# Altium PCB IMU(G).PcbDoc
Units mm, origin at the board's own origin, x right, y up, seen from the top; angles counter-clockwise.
Board outline 35 x 59.99 mm, 2 copper layers (Top Layer, Bottom Layer); 58 components, 99 nets, 240 pads, 60 vias.
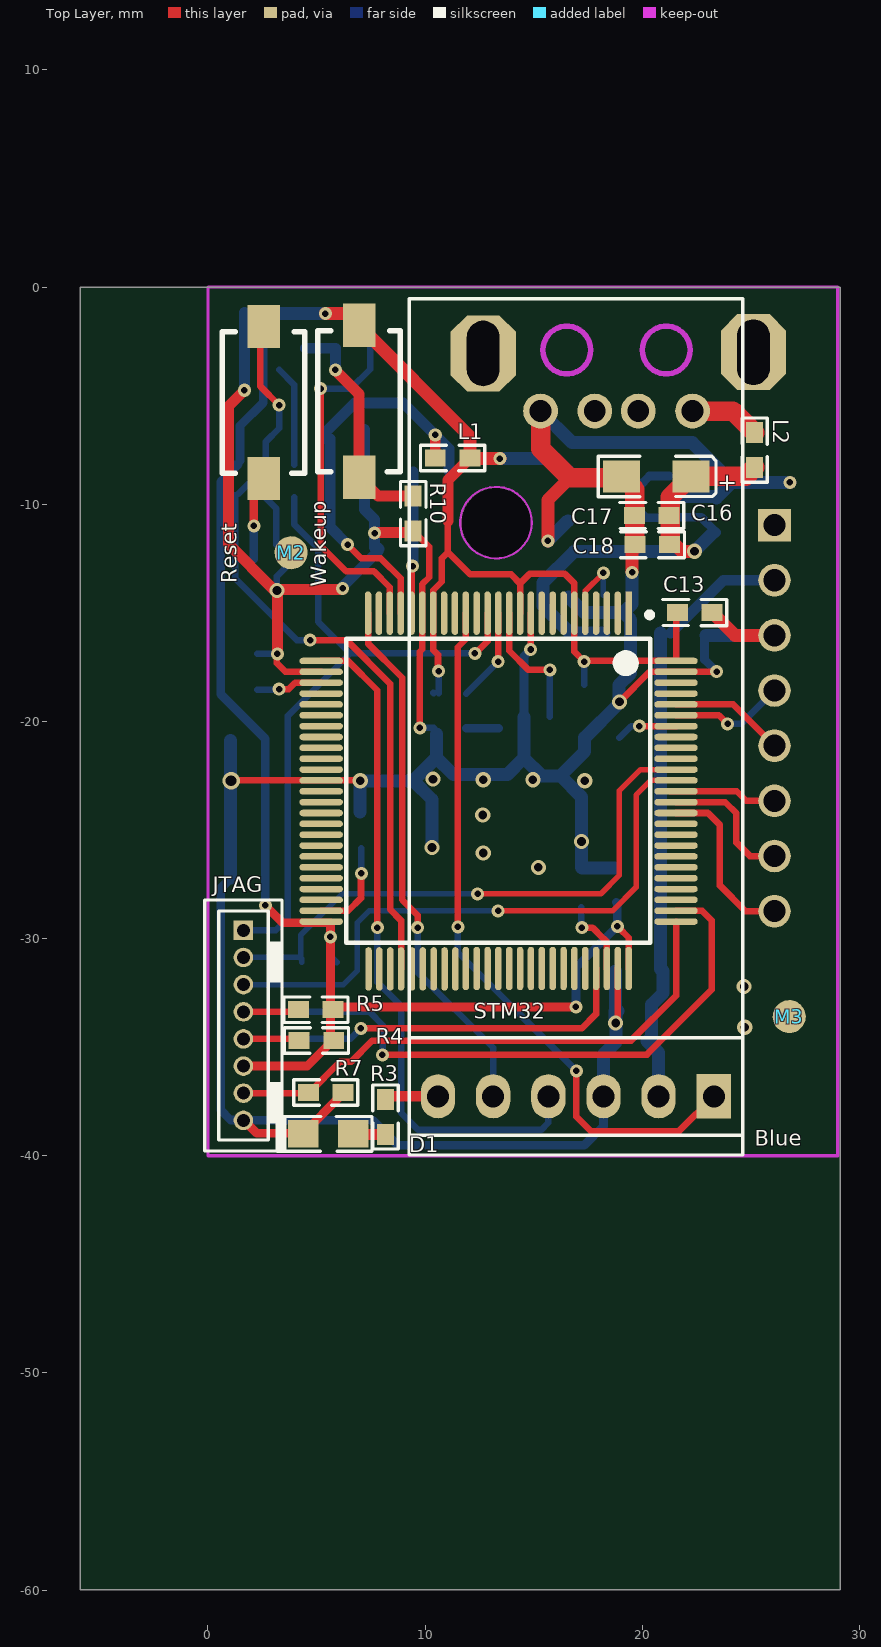
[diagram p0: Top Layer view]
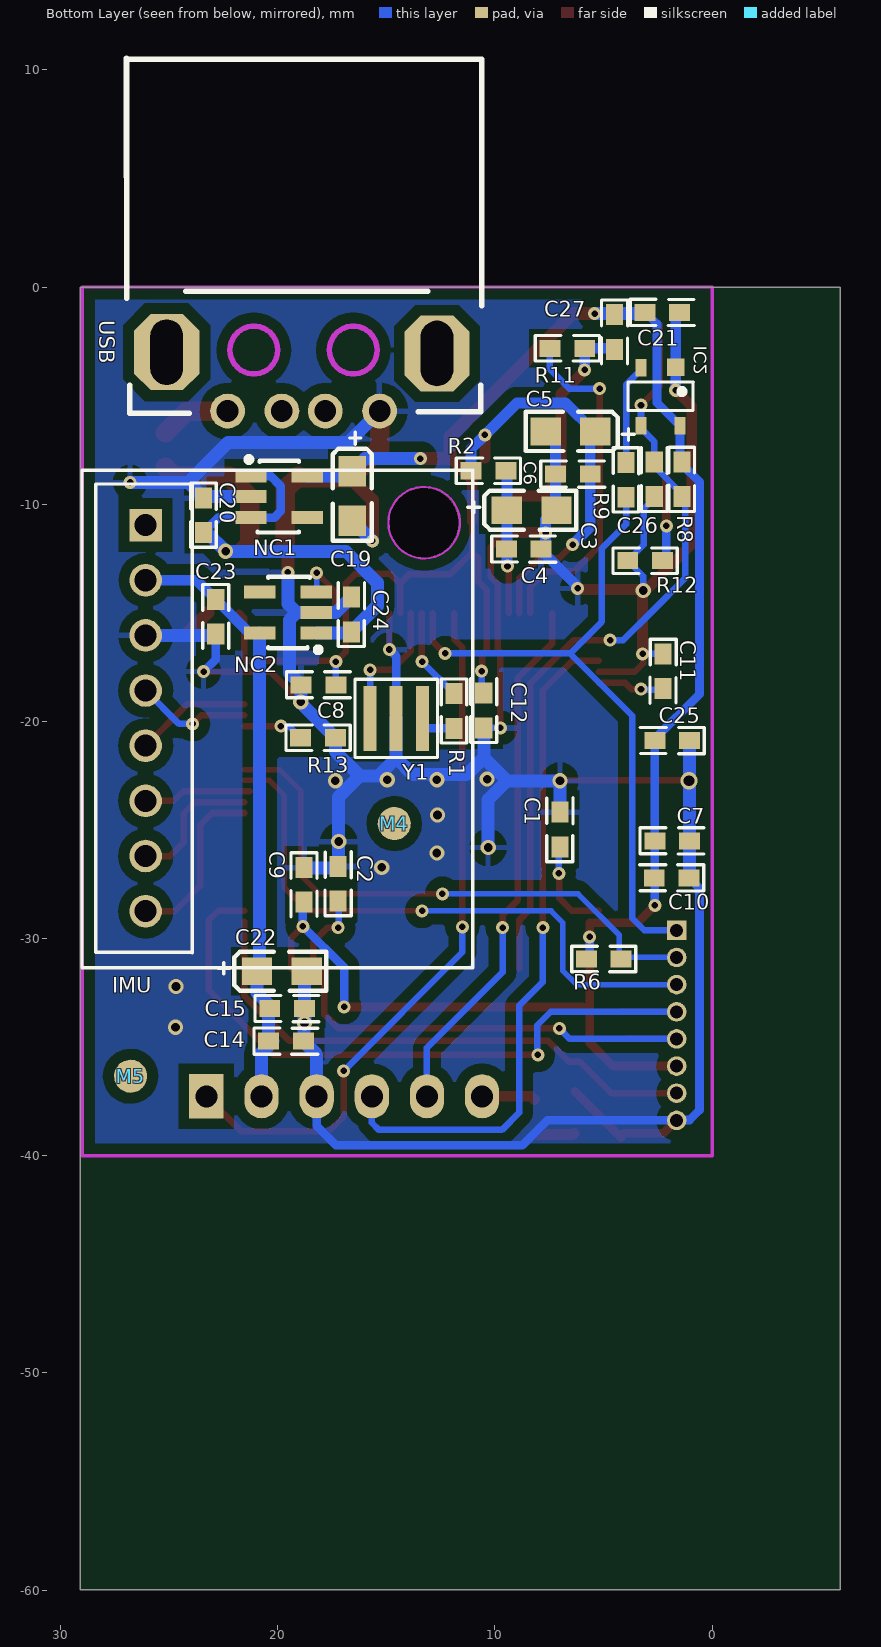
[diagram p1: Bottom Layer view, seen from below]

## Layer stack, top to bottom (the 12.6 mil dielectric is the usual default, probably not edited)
Top Layer: signal copper 0.0356
Dielectric: core 0.32, FR-4, Dk 4.8
Bottom Layer: signal copper 0.0356

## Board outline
-5.893,0 29.108,0 29.108,-59.995 -5.893,-59.995

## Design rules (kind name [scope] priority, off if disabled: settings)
Clearance [All] p1: gap=0.5
PolygonConnect [All] p1: connectstyle=Relief reliefconductorwidth=0.254 reliefentries=4 polygonreliefangle="90 Angle"
RoutingVias [All] p1: holewidth=0.711 width=1.27 viastyle="Through Hole" minholewidth=0.711 minwidth=1.27 maxholewidth=0.711 maxwidth=1.27
SilkscreenOverComponentPads [All] p1: minsilkscreentomaskgap=0.254
SolderMaskExpansion [All] p1: expansion=0.102
Width [All] p1: maxlimit=2.54 minlimit=0.2 preferedwidth=0.254
27 further rules are at their usual default settings.

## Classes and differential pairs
component class IMU_REIO: C25 C26 C27 IC2 M2 M3 M4 M5 M6 R8 R9 R10 R11 R12 R13 R18 Reset S1 S2 Wakeup
component class IMU_POW: C16 C17 C18 C19 C20 C21 C22 C23 C24 C28 C33 L2 NC1 NC2 USB
component class IMU_Blue: Blue Bluetooth C14 C15 D1 IMU JTAG P1 P2 P3 R3 R4 R5 R6 R7
component class CPU_STM32F4: C1 C2 C3 C4 C5 C6 C7 C8 C9 C10 C11 C12 C13 L1 R1 R2 STM32 Y1

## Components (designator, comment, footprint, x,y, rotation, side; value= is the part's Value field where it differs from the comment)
Blue "蓝牙模块" HC-06(35.7*15.2MM) 23.292,-37.262 r180 top locked (schematic designator P2)
C1 "1uF" 0603 7.01,-24.181 r270 bottom
C2 "1uF" 0603 17.221,-26.67 r270 bottom
C3 "1uF/16V" C-0805 8.357,-10.262 r180 bottom
C4 "100n" 0603 7.874,-12.065 r0 bottom
C5 "1uF/16V" C-0805 6.477,-6.655 r0 bottom
C6 "100n" 0603 5.613,-8.611 r0 bottom
C7 "100n" 0603 1.041,-25.502 r0 bottom
C8 "100n" 0603 17.323,-18.313 r0 bottom
C9 "100n" 0603 18.796,-28.321 r90 bottom
C10 "100n" 0603 2.667,-27.203 r180 bottom
C11 "100n" 0603 2.261,-18.491 r90 bottom
C12 "100n" 0603 10.516,-18.694 r270 bottom
C13 "100n" 0603 21.615,-14.986 r0 top
C14 "100n" 0603 18.821,-34.722 r0 bottom
C15 "100n" 0603 18.771,-33.223 r0 bottom
C16 "47uF/10V" C-A(3216-18) 22.25,-8.712 r180 top
C17 "100n" 0603 19.634,-10.516 r0 top
C18 "100n" 0603 19.66,-11.862 r0 top
C19 "4u7/10V" C-0805 16.561,-9.576 r270 bottom
C20 "100n" 0603 23.419,-9.703 r270 bottom
C21 "100n" 0603 1.499,-1.168 r0 bottom
C22 "4u7/10V" C-0805 19.863,-31.496 r180 bottom
C23 "100n" 0603 22.86,-15.977 r90 bottom
C24 "100n" 0603 16.612,-14.275 r270 bottom
C25 "100n" 0603 2.642,-20.879 r180 bottom
C26 "100n" 0603 2.667,-8.052 r270 bottom
C27 "100n" 0603 4.496,-2.87 r90 bottom
D1 "LED red" D0805 6.68,-38.989 r180 top
IC2 "MAX6315US26D2-T" TO-253 2.896,-4.47 r270 top
IMU "IMU" GY-85 18.39,-18.542 r180 bottom locked (schematic designator P1)
JTAG "CON-SIP8-2.0" PLUG1.27-8P 1.651,-33.376 r270 top (schematic designator P3)
L1 "22uH" 0603 12.065,-7.874 r180 top
L2 "22uH" 0603 25.171,-6.706 r270 top
M2 "CON-PAD" BAD_MARK 3.835,-12.217 r0 top
M3 "CON-PAD" BAD_MARK 26.772,-33.579 r0 top
M4 "CON-PAD" BAD_MARK 14.63,-24.689 r180 bottom
M5 "CON-PAD" BAD_MARK 26.772,-36.322 r180 bottom
NC1 "NCP603SN330T1G" TSSOP-5 20.371,-9.296 r180 bottom
NC2 "NCP603SN330T1G" TSSOP-5 19.101,-15.342 r0 bottom
R1 "390" 0603 11.887,-20.32 r90 bottom
R2 "47" 0603 11.1,-8.458 r180 bottom
R3 "390" 0603 8.179,-39.014 r90 top
R4 "3.9K" 0603 4.191,-34.696 r0 top
R5 "3.9K" 0603 4.166,-33.274 r0 top
R6 "3.9K" 0603 4.191,-30.937 r0 bottom
R7 "3.9K" 0603 6.223,-37.084 r180 top
R8 "47K" 0603 1.397,-9.652 r90 bottom
R9 "3.9K" 0603 3.962,-8.077 r270 bottom
R10 "47K" 0603 9.449,-11.227 r90 top
R11 "1K" 0603 5.867,-2.819 r0 bottom
R12 "10K" 0603 3.886,-12.598 r180 bottom
R13 "10K" 0603 18.948,-20.752 r180 bottom
Reset "Manual Pushbutton" KEY-6*4 2.565,-8.814 r180 top (schematic designator S1)
STM32 "STM32F40x-VG (LQFP100)" "LQFP100 (14*14)" 14.656,-21.768 r270 top locked (schematic designator IC1)
USB "车载转换头" USB-SMT 12.243,-2.997 r0 bottom (schematic designator J(USB)1)
Wakeup "Manual Pushbutton" KEY-6*4 6.96,-8.763 r180 top (schematic designator S2)
Y1 "8Mhz" XT-3.2*1.5 15.748,-19.863 r180 bottom

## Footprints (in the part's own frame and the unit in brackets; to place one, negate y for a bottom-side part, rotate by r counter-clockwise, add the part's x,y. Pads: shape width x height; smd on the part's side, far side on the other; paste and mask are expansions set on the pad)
0603 [mil]
  rect 38x31 smd: 1(0,0) 2(63,0)
  silkscreen extent -26,-24 90,24
BAD_MARK [mil] "MARK 点"
  round 60 smd mask+29.53: 0(-0.25,-0.63)
C-0805 [mm]
  rect 1.4x1.27 smd: 1(-1.096,-0.007) 2(1.19,-0.007)
  silkscreen extent -2.89,-0.91 2.1,0.92
C-A(3216-18) [mm]
  rect 1.7x1.47 smd: 1(0,0) 2(3.2,0)
  silkscreen extent -1.14,-0.92 4.28,0.94
D0805 [mm]
  rect 1.4x1.27 smd: A(0,0) K(2.286,0)
  silkscreen extent -0.87,-0.8 3.5,0.8
GY-85 [mm]
  round 3.2 hole 3.2: 0(5.12,7.698)
  rect 1.5x1.5 hole 1.016: 1(-7.697,7.584)
  round 1.5 hole 1.016: 2(-7.697,5.044) 3(-7.697,2.504) 4(-7.697,-0.036) 5(-7.697,-2.576) 6(-7.697,-5.116) 7(-7.697,-7.656) 8(-7.697,-10.196)
  silkscreen extent -10.63,-12.8 7.37,10.11
HC-06(35.7*15.2MM) [mil] "蓝牙模块"
  rect 62x80 hole 40: 1(0,0)
  oval 62x80 hole 40: 2(100,0) 3(200,0) 4(300,0) 5(400,0) 6(500,0)
  silkscreen extent -52,-1446 552,106
KEY-6*4 [mm] "2PIN"
  rect 1.5x2 smd: 1(0,0) 2(0,-7)
  silkscreen extent -1.9,-6.75 1.9,-0.25
"LQFP100 (14*14)" [mm]
  rect 2x0.3 smd: 1(-6.751,4.716)
  oval 2x0.3 smd: 2(-6.751,4.216) 3(-6.751,3.716) 4(-6.751,3.216) 5(-6.751,2.716) 6(-6.751,2.216) 7(-6.751,1.716) 8(-6.751,1.216) 9(-6.751,0.716) 10(-6.751,0.216) 11(-6.751,-0.284) 12(-6.751,-0.784) 13(-6.751,-1.284) 14(-6.751,-1.784) 15(-6.751,-2.284) 16(-6.751,-2.784) 17(-6.751,-3.284) 18(-6.751,-3.784) 19(-6.751,-4.284) 20(-6.751,-4.784) 21(-6.751,-5.284) 22(-6.751,-5.784) 23(-6.751,-6.284) 24(-6.751,-6.784) 25(-6.751,-7.284) 51(9.629,-7.264) 52(9.629,-6.764) 53(9.629,-6.264) 54(9.629,-5.764) 55(9.629,-5.264) 56(9.629,-4.764) 57(9.629,-4.264) 58(9.629,-3.764) 59(9.629,-3.264) 60(9.609,-2.784) 61(9.609,-2.284) 62(9.609,-1.784) 63(9.609,-1.284) 64(9.609,-0.784) 65(9.609,-0.284) 66(9.609,0.216) 67(9.609,0.716) 68(9.609,1.216) 69(9.609,1.716) 70(9.609,2.216) 71(9.609,2.716) 72(9.609,3.216) 73(9.609,3.716) 74(9.609,4.216) 75(9.609,4.716)
  oval 0.3x2 smd: 26(-4.551,-9.444) 27(-4.051,-9.444) 28(-3.551,-9.444) 29(-3.051,-9.444) 30(-2.551,-9.444) 31(-2.051,-9.444) 32(-1.551,-9.444) 33(-1.051,-9.444) 34(-0.551,-9.444) 35(-0.051,-9.444) 36(0.449,-9.444) 37(0.949,-9.444) 38(1.449,-9.444) 39(1.949,-9.444) 40(2.449,-9.444) 41(2.949,-9.444) 42(3.449,-9.444) 43(3.949,-9.444) 44(4.449,-9.444) 45(4.949,-9.444) 46(5.449,-9.444) 47(5.949,-9.444) 48(6.449,-9.444) 49(6.949,-9.444) 50(7.449,-9.444) 76(7.449,6.896) 77(6.949,6.896) 78(6.449,6.896) 79(5.949,6.896) 80(5.449,6.896) 81(4.949,6.896) 82(4.449,6.896) 83(3.949,6.896) 84(3.449,6.896) 85(2.949,6.896) 86(2.449,6.896) 87(1.949,6.896) 88(1.449,6.896) 89(0.949,6.896) 90(0.449,6.896) 91(-0.051,6.896) 92(-0.551,6.896) 93(-1.051,6.896) 94(-1.551,6.896) 95(-2.051,6.896) 96(-2.551,6.896) 97(-3.051,6.896) 98(-3.551,6.896) 99(-4.051,6.896) 100(-4.551,6.896)
  silkscreen extent -6.8,-8.28 8.43,5.8
PLUG1.27-8P [mm]
  rect 0.9x0.9 hole 0.6: 1(-3.756,-0.019)
  round 0.9 hole 0.6: 2(-2.506,-0.019) 3(-1.256,-0.019) 4(-0.006,-0.019) 5(1.244,-0.019) 6(2.494,-0.019) 7(3.744,-0.019) 8(4.994,-0.019)
  silkscreen extent -5.15,-1.8 6.4,1.76
TO-253 [mm]
  rect 0.8x0.8 smd far side: 1(-0.781,-1.219)
  rect 0.8x0.5 smd far side: 2(-0.761,0.381) 3(1.919,0.381) 4(1.919,-1.419)
TSSOP-5 [mm]
  rect 1.45x0.6 smd: 1(-0.864,0.595) 2(-0.864,-0.355) 3(-0.864,-1.305) 4(1.736,-1.305) 5(1.736,0.595)
  silkscreen extent -1.09,-2 1.34,1.48
USB-SMT [mm]
  oct 3x3.5 hole 1.5 slot 3 at 90 deg: 0(0.43,0.058) 0(12.874,0)
  round 1.6 hole 1: 1(3.07,2.71) 2(5.57,2.71) 3(7.57,2.71) 4(10.07,2.71)
  Keep-Out Layer circle w0.254: c4.28,-0.1 r1.1
  Keep-Out Layer circle w0.254: c8.86,-0.1 r1.1
  silkscreen extent -1.63,-13.55 14.74,2.81
XT-3.2*1.5 [mm] "3.2*1.3*0.4mm"
  rect 0.6x3 smd: 1(0,0) 2(1.2,0) 3(2.4,0)
  silkscreen extent -0.7,-1.8 3.1,1.8

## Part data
Blue: library part CON-SIP6-2.54, "单排针6PIN"
C1 C2 C4 C6 C7 C8 C9 C10 C11 C12 C13 C18 C25 C26 C27: library part Cap, "TANTAMOUNT? 595D Vishay Sprague,50V,22.5mOhm"
C3 C5 C16 C19 C22: library part C-A(3216-18)
C14 C15 C21 C24: library part C-SMD
C17: library part C-SMD电容
C20: library part C
C23: library part "Cap Semi", "Capacitor (Semiconductor SIM Model)"
D1: library part diode-LED, "LED"
IC2: library part "MAX 6468", "MAX 6468XS16D3 Reset and Supervisory Circuit"
IMU: library part CON8-2.54, "(栅)围栏式立(卧)8PIN"
JTAG: "单排针8PIN"
L1: library part Inductor, "fcm1608-0603"
L2: library part INDUCTOR
NC1 NC2: library part NCP551
R1 R2 R8 R9 R10 R11 R12 R13: library part Res3, "Resistor"
R3: library part R-0603, "0603(SMD)"
R4 R5 R6 R7: library part R-0805, "0805(SMD)"
Reset Wakeup: library part 微动开关
STM32: library part STM32F40x-VG
USB: library part CON-USB1, "USB"
Y1: library part CRYSTAL-X3, "3PIN"

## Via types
v1: diameter 0.6, hole 0.3, Top Layer to Bottom Layer, 43 vias
v2: diameter 0.7, hole 0.4, Top Layer to Bottom Layer, 16 vias
v3: diameter 0.8, hole 0.5, Top Layer to Bottom Layer, 1 vias

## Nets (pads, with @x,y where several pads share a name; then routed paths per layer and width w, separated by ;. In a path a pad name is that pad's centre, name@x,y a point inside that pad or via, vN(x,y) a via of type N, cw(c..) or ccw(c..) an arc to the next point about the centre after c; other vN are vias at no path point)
"BOOT0 (VPP)": R13.1 STM32.94 | length 2.9
  Top Layer w0.3: v1@19.837,-20.218 19.839,-20.217 STM32.94
  Bottom Layer w0.3: R13.1 19.482,-20.218 v1(19.863,-20.218)
CAR_5V: C16.1 C17.2 C18.2 C20.2 C24.2 L2.2 NC1.1 NC1.3 NC2.1 | length 27.7
  Top Layer w0.6: C18.2@21.285,-11.633 21.819,-12.167 v2(22.403,-12.167)
  Top Layer w0.9: C18.2@21.285,-11.633 21.285,-9.677 C16.1 24.765,-8.712 L2.2
  Bottom Layer w0.4: NC1.1 20.331,-8.701 19.863,-9.169 19.863,-10.312 20.168,-10.617 21.219,-10.617 NC1.3 22.717,-10.601 C20.2
  Bottom Layer w0.6: NC2.1 16.673,-15.937 C24.2 15.418,-14.681 15.418,-13.614 16.859,-12.174 v2@22.428,-12.174 ; v2(22.403,-12.167) C20.2@23.266,-11.303
GND: Blue.3 C1.1 C2.1 C3.2 C4.1 C5.2 C6.2 C7.1 C8.2 C9.2 C10.2 C11.2 C12.2 C13.2 C14.1 C15.1 C16.2 C17.1 C18.1 C19.2 C20.1 C21.1 C22.2 C23.1 C24.1 C25.2 C26.2 D1.K IC2.1 IMU.3 JTAG.8 NC1.2 NC2.2 R7.1 R10.1 R12.1 R13.2 STM32.10 STM32.20 STM32.27 STM32.37 STM32.74 STM32.99 USB.1 Y1.2 | length 196.4
  Top Layer w0.3: v3@1.016,-22.717 STM32.37 v2@7.036,-22.717 ; v1@3.175,-16.84 3.175,-17.323 3.569,-17.717 STM32.27 ; v2(3.175,-13.97) 3.175,-13.945 v2@3.2,-13.919 ; v1@6.198,-13.919 v1@6.198,-13.818 ; R10.1 10.185,-11.963 10.185,-13.36 9.872,-13.674 STM32.20 ; v1(9.754,-20.295) 9.754,-16.789 9.872,-16.671 STM32.20 ; 9.872,-16.366 STM32.20 ; v1@14.872,-16.688 STM32.10 ; v2@18.872,-33.757 STM32.74 ; v2(18.948,-19.101) 20.332,-17.717 STM32.99 v1@23.444,-17.717
  Top Layer w0.4: JTAG.8@1.645,-38.369 2.239,-38.964 D1.K@4.064,-38.964 ; D1.K@4.191,-39.167 R7.1@6.325,-37.033 ; v1@26.746,-8.992 v1(26.797,-8.992)
  Top Layer w0.5: v1(1.676,-4.75) 0.94,-5.486 0.94,-11.836 v2@3.023,-13.919 ; v1@3.2,-16.815 v2@3.2,-13.945 ; v2@3.2,-13.919 v1@6.198,-13.919 ; v1@7.671,-11.303 9.373,-11.303 R10.1
  Top Layer w0.6: v1(15.646,-11.684) 15.646,-9.804 16.662,-8.788 ; v1@19.533,-13.106 C18.1@19.533,-11.633 ; C13.2 24.268,-16.038 IMU.3
  Top Layer w0.9: USB.1@15.262,-6.063 USB.1@15.265,-6.066 ; USB.1 15.313,-7.439 16.662,-8.788 18.974,-8.788 C16.2 19.66,-9.321 C18.1
  Bottom Layer w0.3: C11.2 v1(3.2,-16.891) v1@3.302,-16.891 ; C26.2@2.667,-9.728 3.15,-10.211 3.15,-11.862 R12.1 3.175,-13.31 v2(3.175,-13.97) ; v1@9.627,-20.295 v1(9.754,-20.295) C12.2@10.389,-20.295
  Bottom Layer w0.4: C10.2 0.584,-27.686 0.584,-37.897 1.041,-38.354 1.629,-38.354 JTAG.8@1.645,-38.369 ; JTAG.8 JTAG.8@1.645,-38.369 ; Y1.2@14.548,-19.787 14.548,-16.999 v1(14.859,-16.688) ; Blue.3 18.212,-38.633 17.323,-39.522 8.738,-39.522 7.585,-38.369 JTAG.8@1.645,-38.369 ; C23.1@22.922,-16.038 C23.1 22.86,-17.145 v1(23.419,-17.704)
  Bottom Layer w0.5: v1(1.676,-4.75) IC2.1 ; IC2.1 C21.1@1.677,-1.168 ; v1@6.147,-13.843 C4.1@7.823,-12.167 ; C5.2@7.214,-6.553 C6.2 7.214,-10.239 7.671,-10.697 v1(7.671,-11.328) ; C4.1@7.671,-11.989 v1(7.671,-11.328) ; v1@7.671,-11.303 v1(7.671,-11.328) ; C4.1@7.798,-11.989 C4.1
  Bottom Layer w0.6: C25.2 C7.1 1.041,-27.178 C10.2 ; v2@6.985,-22.733 v2(7.01,-22.733) ; C1.1 v2(7.01,-22.733) ; v2(10.312,-25.806) 10.312,-23.597 9.449,-22.733 ; C12.2@10.516,-20.574 10.516,-21.666 ; Y1.2@14.548,-19.787 Y1.2 14.548,-21.685 ; USB.1 16.768,-7.163 22.301,-7.163 24.13,-8.992 ; v1@15.65,-11.684 C19.2 ; C24.1 17.323,-14.987 NC2.2 19.127,-14.987 ; Blue.3 18.212,-35.331 C14.1 ; C9.2@18.72,-26.746 17.221,-26.746 17.196,-26.721 v2(17.196,-25.527) 17.196,-23.47 16.231,-22.504 ; v2@18.745,-33.757 C15.1@18.745,-33.324 ; C15.1 C15.1@18.872,-33.324 ; C15.1@18.771,-33.122 C22.2@18.771,-31.503 ; C14.1@18.796,-34.722 C15.1@18.796,-33.553 ; v1@19.533,-13.208 19.533,-14.581 19.127,-14.987 ; NC1.2 23.367,-9.651 C20.1 24.13,-8.992 ; C23.1@22.922,-16.038 IMU.3 ; v1(26.797,-8.992) 24.13,-8.992 ; v2(7.01,-22.733) 9.449,-22.733 ; 9.449,-22.733 10.516,-21.666 ; 10.516,-21.666 11.303,-22.454 13.78,-22.454 14.548,-21.685 ; 14.548,-21.685 15.367,-22.504 16.231,-22.504 ; 16.231,-22.504 17.348,-21.387 R13.2 18.923,-19.177 C8.2 19.462,-17.775 19.462,-15.322 19.127,-14.987
  other v1: 6.198,-13.868 19.533,-13.132
  other v2: 24.714,-34.087 18.771,-33.884 24.689,-32.207 15.215,-26.721 12.675,-26.06 12.649,-24.308 17.348,-22.733 12.675,-22.682 14.961,-22.682 10.363,-22.657
  other v3: 1.067,-22.733
NetC27_1: C27.1 R10.2 R11.1 Wakeup.1 | length 10.6
  Top Layer w0.5: v1@5.867,-3.835 6.96,-4.928 Wakeup.1 7.823,-9.627 R10.2
  Bottom Layer w0.5: C27.1@4.496,-2.819 R11.1 v1(5.867,-3.81)
NetD1_A: D1.A R3.1 | length 1.8
  Top Layer w0.5: D1.A@6.35,-38.964 6.401,-39.014 R3.1
NetIC2_2: IC2.2 R9.1 | length 4.7
  Bottom Layer w0.3: IC2.2@3.277,-3.81 3.962,-4.496 R9.1@3.962,-8.179
NetJ(USB)1_4: L2.1 USB.4 | length 3.3
  Top Layer w0.9: USB.4 24.173,-5.707 L2.1
NetP2_6: Blue.6 R3.2 | length 2.5
  Top Layer w0.5: R3.2 8.331,-37.262 Blue.6
NetR1_1: R1.1 Y1.3 | length 1.5
  Bottom Layer w0.4: R1.1 Y1.3@13.391,-20.32
NetR12_2: R12.2 Reset.1 | length 3.7
  Top Layer w0.4: v1(2.108,-10.998) Reset.1@2.108,-8.814
  Bottom Layer w0.4: R12.2@2.108,-12.522 v1(2.108,-10.998)
NRST: JTAG.1 R9.2 STM32.14 | length 31.7
  Top Layer w0.3: v1@12.319,-16.866 12.872,-16.313 STM32.14
  Bottom Layer w0.3: JTAG.1@1.645,-29.619 3.121,-29.619 3.683,-29.058 3.683,-19.736 6.553,-16.866 ; R9.2 3.962,-10.922 5.08,-12.04 5.08,-15.418 6.528,-16.866 6.553,-16.866 ; v1(12.294,-16.866) 6.553,-16.866
PA0: R11.2 STM32.23 | length 16
  Top Layer w0.3: v1(5.182,-4.674) 5.182,-11.913 5.905,-12.636 6.356,-13.087 7.641,-13.087 8.372,-13.818 STM32.23
  Bottom Layer w0.3: v1(5.182,-4.674) 6.579,-4.674 7.468,-3.785 R11.2
PA1: STM32.24
PA2: Blue.5 STM32.25 | length 25.6
  Top Layer w0.3: STM32.25 7.372,-16.414 8.941,-17.983 8.941,-23.927 ; 8.941,-24.892 8.941,-23.927 ; v1@9.652,-29.464 9.652,-28.931 8.941,-28.219 8.941,-23.927
  Bottom Layer w0.3: v1@9.652,-29.464 v1(9.652,-29.489) 9.652,-31.547 13.132,-35.027 Blue.5
PA3: Blue.4 STM32.26 | length 31.6
  Top Layer w0.3: STM32.26 6.447,-17.217 7.798,-18.567 v1(7.798,-29.489) v1@7.798,-29.54
  Bottom Layer w0.3: v1@7.798,-29.464 v1(7.798,-29.489) 7.798,-32.004 8.89,-33.096 8.89,-38.024 9.677,-38.811 15.342,-38.811 15.672,-38.481 Blue.4
PA4: STM32.29
PA5: STM32.30
PA6: STM32.31
PA7: STM32.32
PA8: STM32.67
PA9: STM32.68
PA10: STM32.69
PA11: STM32.70
PA12: STM32.71
PA13: JTAG.5 R4.1 STM32.72 | length 21.1
  Top Layer w0.3: JTAG.5@1.645,-34.619 R4.1@3.937,-34.619 ; v1(7.036,-34.138) 17.211,-34.138 17.872,-33.477 STM32.72 ; v1@7.087,-34.011 v1@7.112,-34.011
  Bottom Layer w0.3: JTAG.5@1.645,-34.619 6.554,-34.619 7.01,-34.163 v1@7.01,-34.112
PA14: JTAG.7 R7.2 STM32.76 | length 25.2
  Top Layer w0.3: JTAG.7 4.587,-37.119 4.648,-37.109 6.096,-35.662 6.604,-35.662 7.569,-34.696 19.482,-34.696 21.552,-32.626 STM32.76
PA15: JTAG.4 R5.1 STM32.77 | length 31.9
  Top Layer w0.3: JTAG.4 4.146,-33.369 R5.1@4.166,-33.35 ; v1@8.103,-35.357 20.218,-35.357 ; 20.244,-35.306 23.19,-32.36 23.19,-29.159 22.748,-28.717 STM32.77
  Bottom Layer w0.3: JTAG.4 7.436,-33.369 8.052,-33.985 8.052,-34.29 v1@8.052,-35.408
  other v1: 8.026,-35.357
PB0: STM32.35
PB1: STM32.36
PB3: JTAG.3 STM32.89 | length 27.6
  Top Layer w0.254: v1(13.36,-28.727) 18.618,-28.727 19.71,-27.635 19.71,-23.393 20.387,-22.717 STM32.89
  Bottom Layer w0.254: JTAG.3@1.645,-32.119 6.235,-32.119 6.883,-31.471 6.883,-29.261 7.417,-28.727 v1(13.36,-28.727) v1@13.411,-28.727
PB4: JTAG.2 R6.1 STM32.90 | length 26.4
  Top Layer w0.254: v1(12.421,-27.94) 18.085,-27.94 18.948,-27.076 18.948,-23.19 19.922,-22.217 STM32.90
  Bottom Layer w0.254: JTAG.2@1.645,-30.869 R6.1@4.098,-30.869 ; R6.1@4.267,-30.937 4.267,-29.845 6.172,-27.94 v1@12.446,-27.94 ; R6.1@4.318,-31.09 R6.1@4.318,-30.937
PB5: STM32.91
PB6: STM32.92
PB7: STM32.93
PB8: IMU.4 STM32.95 | length 5.3
  Top Layer w0.3: STM32.95 23.527,-19.717 v1(23.927,-20.117)
  Bottom Layer w0.3: v1(23.927,-20.117) 24.548,-20.117 IMU.4
PB9: IMU.5 STM32.96 | length 5.3
  Top Layer w0.3: STM32.96 24.185,-19.217 IMU.5
PB10: STM32.47
PB11: STM32.48
PB12: STM32.51
PB13: STM32.52
PB14: STM32.53
PB15: C26.1 IC2.3 R8.1 Reset.2 STM32.54 | length 37.1
  Top Layer w0.3: Reset.2@2.413,-1.738 2.413,-4.572 v1(3.277,-5.436) ; v1(4.699,-16.256) 6.375,-16.256 8.382,-18.263 8.382,-23.927 ; 8.382,-24.511 8.382,-23.927 ; STM32.54 8.892,-29.161 8.382,-28.651 8.382,-23.927
  Bottom Layer w0.3: R8.1@1.245,-9.576 1.245,-13.411 2.819,-14.986 ; R8.1@1.397,-9.525 2.667,-8.255 2.667,-7.112 3.277,-6.502 v1@3.277,-5.447 ; 3.746,-15.913 2.819,-14.986 ; v1(4.699,-16.256) 4.089,-16.256 2.819,-14.986
PC0: STM32.15
PC1: Blue.1 STM32.16 | length 32.9
  Top Layer w0.3: v1(11.506,-29.464) 11.506,-16.586 11.872,-16.221 STM32.16 ; v1@16.967,-36.017 v1(16.967,-36.093) 16.967,-38.202 17.628,-38.862 21.692,-38.862 Blue.1
  Bottom Layer w0.3: v1(11.506,-29.464) 11.506,-30.632 v1(16.967,-36.093)
PC2: STM32.17
PC3: STM32.18
PC4: STM32.33
PC5: STM32.34
PC6: STM32.63
PC7: STM32.64
PC8: STM32.65
PC9: STM32.66
PC10: STM32.78
PC11: STM32.79
PC12: STM32.80
PC13: STM32.7
PC14: STM32.8
PC15: STM32.9
PD0: STM32.81
PD1: STM32.82
PD2: STM32.83
PD3: STM32.84
PD4: STM32.85
PD5: IMU.8 STM32.86 | length 8
  Top Layer w0.3: STM32.86 23.023,-24.217 23.571,-24.765 23.571,-27.559 24.75,-28.738 IMU.8
PD6: IMU.7 STM32.87 | length 6.4
  Top Layer w0.3: STM32.87 23.26,-23.717 23.818,-23.717 24.333,-24.232 24.333,-25.578 24.954,-26.198 IMU.7
PD7: IMU.6 STM32.88 | length 5
  Top Layer w0.3: STM32.88@21.285,-23.217 22.682,-23.217 24.349,-23.217 24.79,-23.658 IMU.6
PD8: STM32.55
PD9: STM32.56
PD10: STM32.57
PD11: STM32.58
PD12: STM32.59
PD13: STM32.60
PD14: STM32.61
PD15: STM32.62
PE0: STM32.97
PE1: STM32.98
PE2: STM32.1
PE3: STM32.2
PE4: STM32.3
PE5: STM32.4
PE6: NC2.3 STM32.5 | length 3.2
  Top Layer w0.254: STM32.5 17.372,-13.992 18.207,-13.157 v1(18.212,-13.157)
  Bottom Layer w0.254: NC2.3@18.212,-14.189 v1(18.212,-13.157)
PE7: STM32.38
PE8: STM32.39
PE9: STM32.40
PE10: STM32.41
PE11: STM32.42
PE12: STM32.43
PE13: STM32.44
PE14: STM32.45
PE15: STM32.46
"PH0-OSC_IN (OSC_IN)": STM32.12 Y1.1 | length 6.1
  Top Layer w0.3: STM32.12 13.872,-16.742 14.757,-17.628 v1@15.723,-17.628
  Bottom Layer w0.3: Y1.1@15.748,-19.787 v1@15.748,-17.653
  other v1: 15.748,-17.628
"PH1-OSC_OUT (OSC_OUT)": R1.2 STM32.13 | length 4.3
  Top Layer w0.3: v1@13.372,-17.297 STM32.13
  Bottom Layer w0.3: R1.2 v1@13.348,-17.259
  other v1: 13.36,-17.247
VBAT: C7.2 C8.1 C9.1 C10.1 C12.1 C13.1 C19.1 C21.2 C25.1 C27.2 IC2.4 JTAG.6 L1.1 NC1.5 R4.2 R5.2 R6.2 R8.2 STM32.6 STM32.11 STM32.19 STM32.50 STM32.75 STM32.100 Wakeup.2 | length 113.6
  Top Layer w0.3: v1@10.541,-17.678 10.592,-17.628 10.592,-16.933 10.372,-16.713 STM32.19 10.372,-13.96 10.762,-13.57 10.762,-12.497 11.049,-12.209 ; 11.049,-11.938 11.049,-11.582 ; 11.049,-10.77 11.049,-11.582 ; 12.344,-13.233 13.005,-13.233 ; STM32.11 14.372,-13.644 ; v1@17.335,-17.259 v1(17.323,-17.247) ; v1@18.923,-29.515 19.372,-29.964 STM32.75 ; C13.1@21.793,-14.986 21.552,-15.227 STM32.100 17.353,-17.217 v1(17.323,-17.247) ; 11.049,-12.209 12.073,-13.233 13.005,-13.233 ; 11.049,-12.209 11.049,-11.582 ; 13.005,-13.233 13.961,-13.233 14.372,-13.644 ; 14.372,-13.644 14.808,-13.208 16.434,-13.208 16.872,-13.646 STM32.6 16.872,-16.796 v1(17.323,-17.247)
  Top Layer w0.4: JTAG.6@1.645,-35.869 4.572,-35.869 5.639,-34.803 v1(5.639,-29.921) 5.639,-29.267 3.435,-29.267 v1(2.642,-28.473) ; R5.2@5.969,-33.147 v1(16.942,-33.147)
  Top Layer w0.5: 11.049,-10.77 11.049,-8.89 12.04,-7.899 L1.1
  Top Layer w0.6: v1(5.41,-1.219) 6.416,-1.219 Wakeup.2 6.96,-1.778 12.065,-6.883 L1.1 ; L1.1@12.04,-7.899 v1(13.437,-7.899)
  Bottom Layer w0.3: R6.2@5.639,-30.81 R6.2@5.918,-31.09 ; C12.1@10.363,-18.669 C12.1@10.389,-18.694 ; C12.1@10.617,-18.694 v1(10.617,-17.678) ; C8.1 v1(17.323,-17.247)
  Bottom Layer w0.4: R8.2@1.27,-8.204 R8.2@1.27,-8.179 ; R8.2@1.397,-8.153 0.584,-8.966 0.584,-18.745 2.642,-20.803 C25.1 C7.2 v1@2.642,-28.448 ; R8.2@1.477,-7.997 IC2.4 2.54,-5.327 2.54,-1.702 C21.2@3.023,-1.219 ; R6.2@5.639,-30.81 v1(5.639,-29.921) ; v1(16.942,-33.147) 16.942,-31.333 18.837,-29.439 v1(18.847,-29.439) 18.847,-28.372 C9.1
  Bottom Layer w0.6: C21.2@3.048,-1.219 v1@5.385,-1.219 ; v1(13.437,-7.899) 15.987,-7.899 C19.1 ; C19.1@16.568,-8.701 NC1.5
VCAP_1: C1.2 STM32.49 | length 4.4
  Top Layer w0.3: STM32.49 6.462,-28.717 7.046,-28.133 7.046,-27.015 v1(7.061,-27)
  Bottom Layer w0.3: v1(7.061,-27) C1.2@7.061,-25.832
VCAP_2: C2.2 STM32.73 | length 3.8
  Top Layer w0.3: v1(17.221,-29.489) 17.704,-29.489 18.021,-29.807 ; 17.869,-29.654 18.021,-29.807 ; STM32.73 18.372,-30.157 18.021,-29.807
  Bottom Layer w0.3: C2.2@17.196,-28.55 17.196,-29.464 v1(17.221,-29.489)
VDD4: C11.1 STM32.28 | length 3.1
  Top Layer w0.3: v1(3.277,-18.517) 3.708,-18.517 4.008,-18.217 STM32.28
  Bottom Layer w0.3: C11.1@2.261,-18.542 v1@3.277,-18.542
VDD_DEVICE: Blue.2 C14.2 C15.2 C22.1 C23.2 IMU.2 NC2.5 | length 27.7
  Bottom Layer w0.5: NC2.5@21.298,-15.938 C23.2 23.738,-13.498 IMU.2
  Bottom Layer w0.6: C14.2@20.218,-34.722 C14.2@20.46,-34.963 ; Blue.2 20.752,-35.255 C14.2@20.46,-34.963 ; C22.1@20.837,-31.394 NC2.5 ; C22.1 20.959,-32.508 20.422,-33.045 20.422,-34.684 20.46,-34.722 C14.2@20.46,-34.963
VDDA: C5.1 C6.1 L1.2 R2.1 STM32.22 | length 19.4
  Top Layer w0.3: v1(6.426,-11.862) 7.061,-12.497 7.957,-12.497 8.872,-13.411 STM32.22
  Top Layer w0.5: L1.2 v1@10.465,-6.833
  Bottom Layer w0.5: C5.1@5.406,-6.982 5.406,-6.684 6.756,-5.334 8.992,-5.334 v1(10.465,-6.807) 11.1,-7.442 R2.1 ; C5.1@5.613,-6.982 C6.1 5.613,-11.049 v1(6.426,-11.862)
VREF+: C3.1 C4.2 R2.2 STM32.21 | length 6.6
  Top Layer w0.3: STM32.21 9.372,-12.904 v1(9.423,-12.852)
  Bottom Layer w0.3: R2.2@9.449,-8.509 R2.2
  Bottom Layer w0.5: v1@9.449,-12.852 9.449,-12.065 R2.2@9.449,-8.509
pads on no net: IMU.0 IMU.1 M2.0 M3.0 M4.0 M5.0 NC1.4 NC2.4 USB.0 USB.2 USB.3

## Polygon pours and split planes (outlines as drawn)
GND on Bottom Layer "Bottom Layer-No Net" (solid, pour order 1000): 0,0 28.981,0 28.981,-39.954 28.956,-39.98 0.051,-39.98

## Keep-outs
Keep-Out Layer:
  circle w0.1: c13.262,-10.846 r1.648
  lines w0.152: 0,-40 0,0 29,0 29,-40 0,-40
